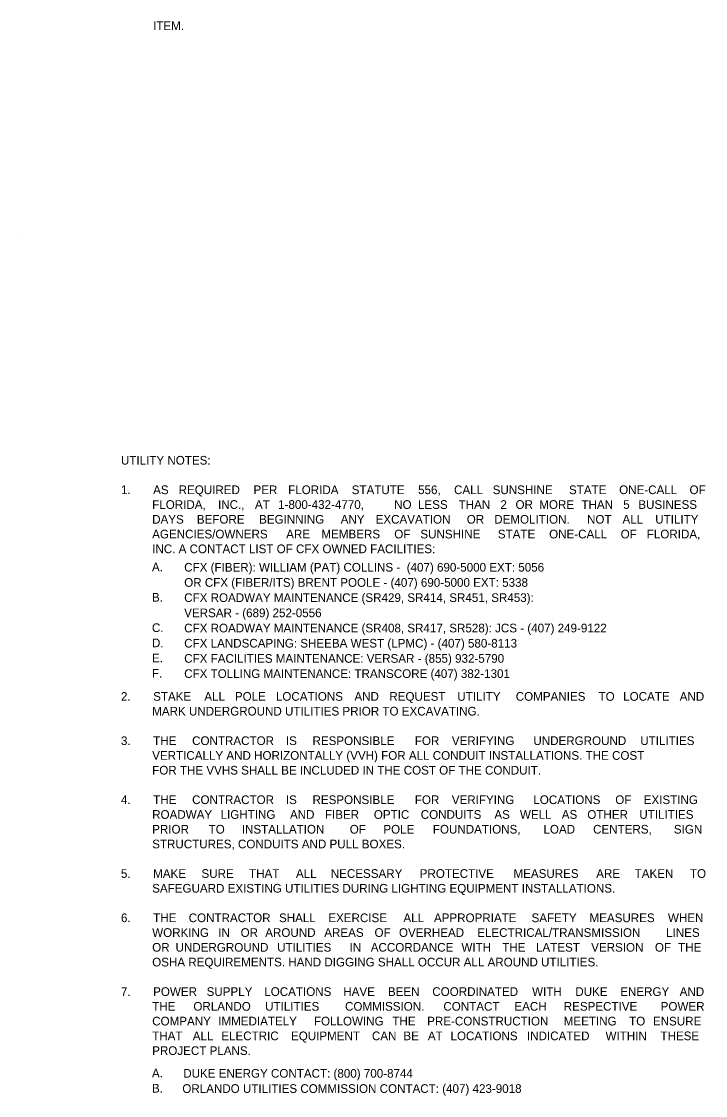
# Model space of a CAD drawing. Extents: x -55 to 2471539, y -90 to 3608906.
# Drawn here: x -54 to 497, y 1661 to 2527 of the extents above; entities that cross this region are included whole.
import ezdxf

# ---------------------------------------------------------------- set-up
doc = ezdxf.new("R2010")
doc.units = 0
doc.layers.add('TextMinor', color=7, linetype='Continuous')
doc.layers.add('XSCell', color=7, linetype='Continuous')

msp = doc.modelspace()

# ---------------------------------------------------------------- linework, layer by layer
at = {"layer": 'TextMinor'}
msp.add_line((-54.3, 2356.32), (-54.3, 2356.32), dxfattribs=at)

# ---------------------------------------------------------------- texts
at = {"layer": 'XSCell'}
for s, p in [('ITEM. ', (51.88, 2519.99)), ('UTILITY NOTES:', (25.93, 2169.7)), ('1.', (25.93, 2145.9)), ('AS ', (51.88, 2145.9)), ('REQUIRED ', (72.45, 2145.9)), ('PER ', (132.84, 2145.9)), ('FLORIDA ', (160.8, 2145.9)), ('STATUTE ', (212.02, 2145.9)), ('556, ', (265.56, 2145.9)), ('CALL ', (294.55, 2145.9)), ('SUNSHINE ', (325.71, 2145.9)), ('STATE ', (387.26, 2145.9)), ('ONE-CALL ', (427.72, 2145.9)), ('OF ', (484.48, 2145.9)), ('FLORIDA, ', (51.12, 2134)), ('INC., ', (104.23, 2134)), ('AT ', (133.98, 2134)), ('1-800-432-4770, ', (152.68, 2134)), ('NO ', (246.28, 2134)), ('LESS ', (265.49, 2134)), ('THAN ', (298.24, 2134)), ('2 ', (331.94, 2134)), ('OR ', (344.13, 2134)), ('MORE ', (363.28, 2134)), ('THAN ', (397.29, 2134)), ('5 ', (430.99, 2134)), ('BUSINESS ', (443.18, 2134)), ('DAYS ', (51.12, 2122.1)), ('BEFORE ', (87.13, 2122.1)), ('BEGINNING ', (137.34, 2122.1)), ('ANY ', (203.14, 2122.1)), ('EXCAVATION ', (231.32, 2122.1)), ('OR ', (304.81, 2122.1)), ('DEMOLITION. ', (326.96, 2122.1)), ('NOT ', (401.82, 2122.1)), ('ALL ', (430.4, 2122.1)), ('UTILITY ', (456.81, 2122.1)), ('AGENCIES/OWNERS ', (51.12, 2110.2)), ('ARE ', (159.16, 2110.2)), ('MEMBERS ', (187.58, 2110.2)), ('OF ', (246.33, 2110.2)), ('SUNSHINE ', (267.4, 2110.2)), ('STATE ', (329.87, 2110.2)), ('ONE-CALL ', (371.24, 2110.2)), ('OF ', (428.91, 2110.2)), ('FLORIDA, ', (449.99, 2110.2)), ('INC. A CONTACT LIST OF CFX OWNED FACILITIES:', (51.12, 2098.3)), ('A.', (50.92, 2083.7)), ('CFX (FIBER): WILLIAM (PAT) COLLINS -  (407) 690-5000 EXT: 5056', (76.93, 2083.43)), ('OR CFX (FIBER/ITS) BRENT POOLE - (407) 690-5000 EXT: 5338', (76.93, 2071.18)), ('B.', (50.92, 2059.2)), ('CFX ROADWAY MAINTENANCE (SR429, SR414, SR451, SR453): ', (76.93, 2058.93)), ('VERSAR - (689) 252-0556', (76.93, 2046.68)), ('C.', (50.92, 2034.7)), ('CFX ROADWAY MAINTENANCE (SR408, SR417, SR528): JCS - (407) 249-9122', (76.93, 2034.43)), ('D.', (50.92, 2022.45)), ('CFX LANDSCAPING: SHEEBA WEST (LPMC) - (407) 580-8113', (76.93, 2022.18)), ('E.', (50.92, 2010.2)), ('CFX FACILITIES MAINTENANCE: VERSAR - (855) 932-5790', (76.93, 2009.93)), ('F.', (50.92, 1997.95)), ('CFX TOLLING MAINTENANCE: TRANSCORE (407) 382-1301', (76.93, 1997.68)), ('2.', (25.93, 1979.3)), ('STAKE ', (51.88, 1979.3)), ('ALL ', (93.17, 1979.3)), ('POLE ', (117.82, 1979.3)), ('LOCATIONS ', (150.88, 1979.3)), ('AND ', (214.2, 1979.3)), ('REQUEST ', (242.38, 1979.3)), ('UTILITY ', (297.2, 1979.3)), ('COMPANIES ', (344.33, 1979.3)), ('TO ', (411.09, 1979.3)), ('LOCATE ', (430.98, 1979.3)), ('AND ', (476.52, 1979.3)), ('MARK UNDERGROUND UTILITIES PRIOR TO EXCAVATING.', (51.12, 1967.4)), ('3.', (25.93, 1943.6)), ('THE ', (51.88, 1943.6)), ('CONTRACTOR ', (83.33, 1943.6)), ('IS ', (158.93, 1943.6)), ('RESPONSIBLE ', (180.41, 1943.6)), ('FOR ', (262.92, 1943.6)), ('VERIFYING ', (292.77, 1943.6)), ('UNDERGROUND ', (358.54, 1943.6)), ('UTILITIES ', (444.75, 1943.6)), ('VERTICALLY AND HORIZONTALLY (VVH) FOR ALL CONDUIT INSTALLATIONS. THE COST ', (51.12, 1931.7)), ('FOR THE VVHS SHALL BE INCLUDED IN THE COST OF THE CONDUIT.', (51.12, 1919.8)), ('4.', (25.93, 1896)), ('THE ', (51.88, 1896)), ('CONTRACTOR ', (83.33, 1896)), ('IS ', (158.92, 1896)), ('RESPONSIBLE ', (180.4, 1896)), ('FOR ', (262.91, 1896)), ('VERIFYING ', (292.75, 1896)), ('LOCATIONS ', (358.52, 1896)), ('OF ', (424.58, 1896)), ('EXISTING ', (447.54, 1896)), ('ROADWAY ', (51.12, 1884.1)), ('LIGHTING ', (106.3, 1884.1)), ('AND ', (162.24, 1884.1)), ('FIBER ', (190.41, 1884.1)), ('OPTIC ', (229.87, 1884.1)), ('CONDUITS ', (267.7, 1884.1)), ('AS ', (327.08, 1884.1)), ('WELL ', (347.7, 1884.1)), ('AS ', (381.42, 1884.1)), ('OTHER ', (402.04, 1884.1)), ('UTILITIES ', (444, 1884.1)), ('PRIOR ', (51.12, 1872.2)), ('TO ', (96.64, 1872.2)), ('INSTALLATION ', (123.39, 1872.2)), ('OF ', (210.46, 1872.2)), ('POLE ', (237.55, 1872.2)), ('FOUNDATIONS, ', (277.47, 1872.2)), ('LOAD ', (366.67, 1872.2)), ('CENTERS, ', (406.69, 1872.2)), ('SIGN ', (471.85, 1872.2)), ('STRUCTURES, CONDUITS AND PULL BOXES.', (51.12, 1860.3)), ('5.', (25.93, 1836.5)), ('MAKE ', (51.88, 1836.5)), ('SURE ', (90.88, 1836.5)), ('THAT ', (129.25, 1836.5)), ('ALL ', (167.06, 1836.5)), ('NECESSARY ', (195.14, 1836.5)), ('PROTECTIVE ', (266.87, 1836.5)), ('MEASURES ', (342.5, 1836.5)), ('ARE ', (409.22, 1836.5)), ('TAKEN ', (440.22, 1836.5)), ('TO ', (484.81, 1836.5)), ('SAFEGUARD EXISTING UTILITIES DURING LIGHTING EQUIPMENT INSTALLATIONS.', (51.12, 1824.6)), ('6.', (25.93, 1800.8)), ('THE ', (51.88, 1800.8)), ('CONTRACTOR ', (80.56, 1800.8)), ('SHALL ', (153.39, 1800.8)), ('EXERCISE ', (193.15, 1800.8)), ('ALL ', (253.73, 1800.8)), ('APPROPRIATE ', (278.35, 1800.8)), ('SAFETY ', (357.05, 1800.8)), ('MEASURES ', (403.81, 1800.8)), ('WHEN ', (467.07, 1800.8)), ('WORKING ', (51.12, 1788.9)), ('IN ', (104.36, 1788.9)), ('OR ', (122.44, 1788.9)), ('AROUND ', (142.3, 1788.9)), ('AREAS ', (189.9, 1788.9)), ('OF ', (230.43, 1788.9)), ('OVERHEAD ', (250.13, 1788.9)), ('ELECTRICAL/TRANSMISSION ', (313.25, 1788.9)), ('LINES ', (465.57, 1788.9)), ('OR ', (51.12, 1777)), ('UNDERGROUND ', (69.97, 1777)), ('UTILITIES ', (151.91, 1777)), ('IN ', (210.32, 1777)), ('ACCORDANCE ', (227.4, 1777)), ('WITH ', (300.52, 1777)), ('THE ', (333.46, 1777)), ('LATEST ', (360.64, 1777)), ('VERSION ', (405.17, 1777)), ('OF ', (456.54, 1777)), ('THE ', (475.23, 1777)), ('OSHA REQUIREMENTS. HAND DIGGING SHALL OCCUR ALL AROUND UTILITIES.', (51.12, 1765.1)), ('7.', (25.93, 1741.3)), ('POWER ', (51.88, 1741.3)), ('SUPPLY ', (95, 1741.3)), ('LOCATIONS ', (141.53, 1741.3)), ('HAVE ', (205.24, 1741.3)), ('BEEN ', (241.22, 1741.3)), ('COORDINATED ', (277.03, 1741.3)), ('WITH ', (357.5, 1741.3)), ('DUKE ', (392.36, 1741.3)), ('ENERGY ', (428.57, 1741.3)), ('AND ', (476.52, 1741.3)), ('THE ', (51.12, 1729.4)), ('ORLANDO ', (84.35, 1729.4)), ('UTILITIES ', (142.2, 1729.4)), ('COMMISSION. ', (206.65, 1729.4)), ('CONTACT ', (285.96, 1729.4)), ('EACH ', (343.21, 1729.4)), ('RESPECTIVE ', (383.03, 1729.4)), ('POWER ', (461.2, 1729.4)), ('COMPANY ', (51.12, 1717.5)), ('IMMEDIATELY ', (104.38, 1717.5)), ('FOLLOWING ', (181.58, 1717.5)), ('THE ', (244.82, 1717.5)), ('PRE-CONSTRUCTION ', (272.86, 1717.5)), ('MEETING ', (383.03, 1717.5)), ('TO ', (435.74, 1717.5)), ('ENSURE ', (454.94, 1717.5)), ('THAT ', (51.12, 1705.6)), ('ALL ', (83.84, 1705.6)), ('ELECTRIC ', (106.84, 1705.6)), ('EQUIPMENT ', (163.06, 1705.6)), ('CAN ', (228.33, 1705.6)), ('BE ', (253.73, 1705.6)), ('AT ', (273.43, 1705.6)), ('LOCATIONS ', (291.71, 1705.6)), ('INDICATED ', (353.38, 1705.6)), ('WITHIN ', (416.73, 1705.6)), ('THESE ', (461.02, 1705.6)), ('PROJECT PLANS.', (51.12, 1693.7)), ('A.', (50.92, 1675.64)), ('DUKE ENERGY CONTACT: (800) 700-8744', (76.18, 1675.37)), ('B.', (50.92, 1663.39)), ('ORLANDO UTILITIES COMMISSION CONTACT: (407) 423-9018', (75.42, 1663.12))]:
    msp.add_text(s, height=7, dxfattribs=at).set_placement(p)

doc.saveas('drawing.dxf')
